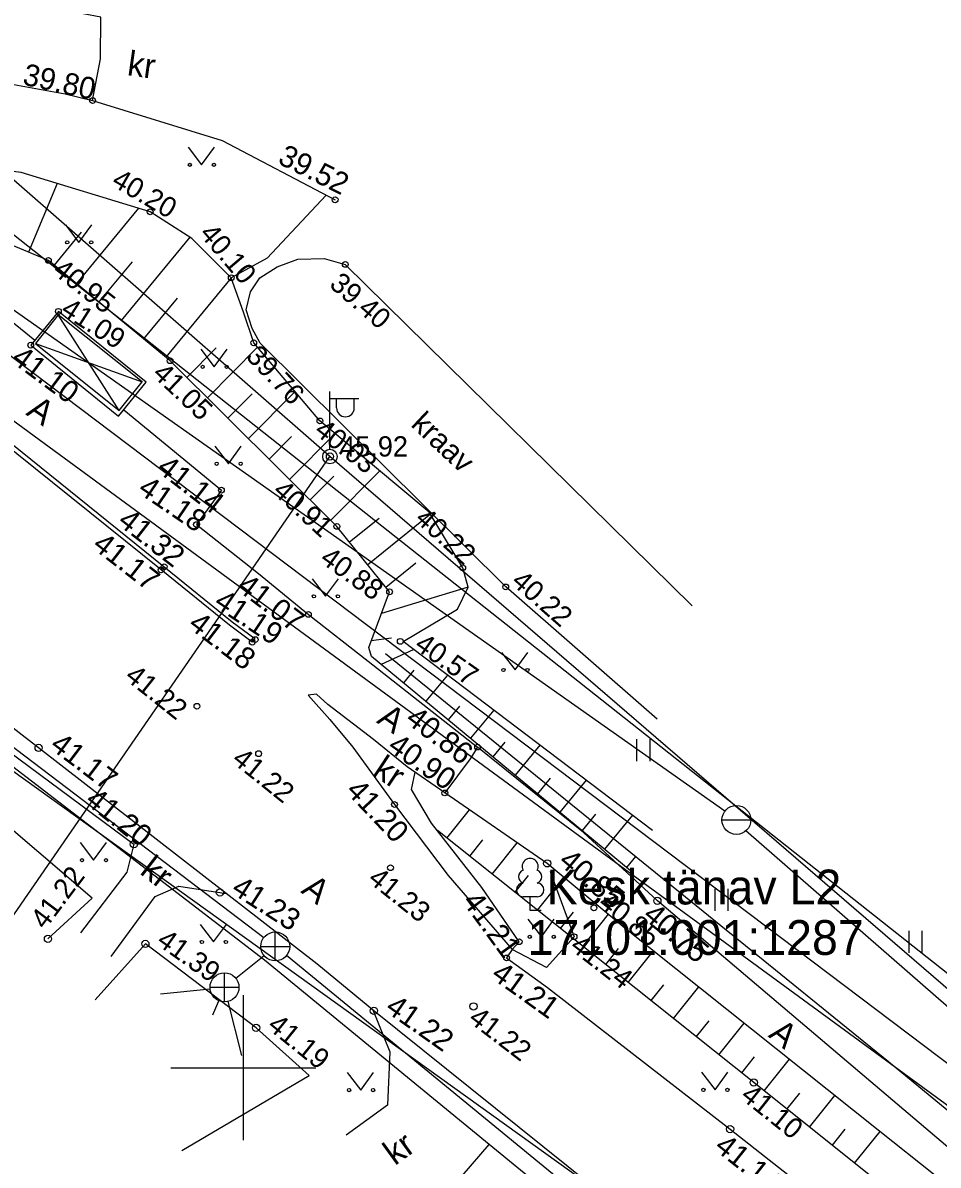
# Model space of a CAD drawing. Extents: x 641898 to 642452, y 6471715 to 6472255.
# Drawn here: x 642092.39 to 642123.98, y 6471996.64 to 6472036.05 of the extents above; entities that cross this region are included whole.
import ezdxf

# ---------------------------------------------------------------- set-up
doc = ezdxf.new("R2010")
doc.units = 0
for name, color, linetype in [('HALJASTUS', 7, 'Continuous'), ('KKAEV', 7, 'Continuous'), ('KORGUS-EH2000', 7, 'Continuous'), ('KTRASS', 7, 'Continuous'), ('MPOHULIIN', 7, 'Continuous'), ('PIIR', 7, 'Continuous'), ('POST', 7, 'Continuous'), ('PUU', 7, 'Continuous'), ('RAJATIS', 7, 'Continuous'), ('RELJEEF', 7, 'Continuous'), ('TEE', 7, 'Continuous'), ('TTRASS', 7, 'Continuous'), ('VEEKOGU', 7, 'Continuous'), ('VKAEV', 7, 'Continuous'), ('VORK', 7, 'Continuous'), ('VTRASS', 7, 'Continuous')]:
    doc.layers.add(name, color=color, linetype=linetype)

msp = doc.modelspace()

# ---------------------------------------------------------------- linework, layer by layer
at = {"layer": 'HALJASTUS'}
for p, q in [((642098.093, 6472031.76), (642098.556, 6472031.154)), ((642098.556, 6472031.154), (642099.002, 6472031.76)), ((642093.86, 6472029.084), (642094.323, 6472028.478)), ((642094.323, 6472028.478), (642094.769, 6472029.084)), ((642098.532, 6472024.791), (642098.996, 6472024.184)), ((642098.996, 6472024.184), (642099.441, 6472024.791)), ((642099.019, 6472021.447), (642099.483, 6472020.84)), ((642099.483, 6472020.84), (642099.928, 6472021.447)), ((642102.374, 6472016.874), (642102.837, 6472016.267)), ((642102.837, 6472016.267), (642103.283, 6472016.874)), ((642108.916, 6472014.333), (642109.379, 6472013.727)), ((642109.379, 6472013.727), (642109.825, 6472014.333)), ((642113.571, 6472011.342), (642113.571, 6472010.581)), ((642114.026, 6472011.342), (642114.026, 6472010.581)), ((642094.367, 6472007.77), (642094.831, 6472007.163)), ((642094.831, 6472007.163), (642095.276, 6472007.77)), ((642116.272, 6472006.171), (642116.272, 6472005.41)), ((642116.728, 6472006.171), (642116.728, 6472005.41)), ((642098.508, 6472004.949), (642098.971, 6472004.342)), ((642098.971, 6472004.342), (642099.417, 6472004.949)), ((642109.824, 6472005.124), (642110.288, 6472004.517)), ((642110.288, 6472004.517), (642110.733, 6472005.124)), ((642122.968, 6472004.731), (642122.968, 6472003.97)), ((642123.423, 6472004.731), (642123.423, 6472003.97)), ((642103.588, 6471999.837), (642104.051, 6471999.23)), ((642104.051, 6471999.23), (642104.497, 6471999.837)), ((642115.818, 6471999.844), (642116.281, 6471999.237)), ((642116.281, 6471999.237), (642116.727, 6471999.844))]:
    msp.add_line(p, q, dxfattribs=at)
for points in [[(642102.863, 6472030.108), (642100.826, 6472027.93), (642099.583, 6472027.26)], [(642132.112, 6471992.094), (642122.27, 6472000.206), (642104.909, 6472014.278)], [(642093.257, 6472004.451), (642094.782, 6472005.85), (642085.481, 6472013.799), (642083.722, 6472011.351)], [(642110.588, 6472006.783), (642110.731, 6472006.388), (642111.416, 6472004.523), (642110.463, 6472003.463), (642109.282, 6472004.08)], [(642097.873, 6471997.144), (642102.276, 6471999.739), (642100.441, 6472001.377), (642096.619, 6472004.274), (642094.883, 6472002.346)]]:
    msp.add_lwpolyline(points, dxfattribs=at)
for centre in [(642098.155, 6472031.154), (642098.984, 6472031.154), (642093.922, 6472028.478), (642094.751, 6472028.478), (642098.595, 6472024.184), (642099.423, 6472024.184), (642099.082, 6472020.84), (642099.91, 6472020.84), (642102.436, 6472016.267), (642103.265, 6472016.267), (642108.978, 6472013.727), (642109.807, 6472013.727), (642094.43, 6472007.163), (642095.259, 6472007.163), (642109.887, 6472004.517), (642110.715, 6472004.517), (642098.57, 6472004.342), (642099.399, 6472004.342), (642103.65, 6471999.23), (642104.479, 6471999.23), (642115.88, 6471999.237), (642116.709, 6471999.237)]:
    msp.add_circle(centre, 0.055, dxfattribs=at)
at = {"layer": 'KKAEV'}
for p, q in [((642101.104, 6472003.687), (642101.104, 6472004.687)), ((642100.604, 6472004.187), (642101.604, 6472004.187)), ((642099.35, 6472002.276), (642099.35, 6472003.276)), ((642098.85, 6472002.776), (642099.85, 6472002.776))]:
    msp.add_line(p, q, dxfattribs=at)
for centre in [(642101.104, 6472004.187), (642099.35, 6472002.776)]:
    msp.add_circle(centre, 0.5, dxfattribs=at)
at = {"layer": 'KORGUS-EH2000'}
for centre, radius in [((642094.797, 6472033.371), 0.1), ((642103.168, 6472029.948), 0.1), ((642096.784, 6472029.532), 0.1), ((642093.272, 6472027.857), 0.1), ((642103.52, 6472027.718), 0.1), ((642099.583, 6472027.26), 0.1), ((642093.616, 6472026.099), 0.1), ((642092.663, 6472024.932), 0.1), ((642100.36, 6472025.014), 0.1), ((642097.472, 6472024.394), 0.1), ((642102.645, 6472022.318), 0.1), ((642102.99, 6472021.089), 0.125), ((642099.243, 6472019.93), 0.1), ((642098.383, 6472018.742), 0.1), ((642103.229, 6472018.679), 0.1), ((642097.162, 6472017.177), 0.1), ((642097.268, 6472017.288), 0.1), ((642107.574, 6472017.251), 0.1), ((642109.056, 6472016.59), 0.1), ((642105.049, 6472016.421), 0.1), ((642102.245, 6472015.643), 0.1), ((642100.309, 6472014.686), 0.1), ((642100.411, 6472014.774), 0.1), ((642105.418, 6472014.713), 0.1), ((642098.399, 6472012.473), 0.1), ((642092.935, 6472011.037), 0.125), ((642108.086, 6472011.066), 0.1), ((642100.527, 6472010.838), 0.1), ((642106.954, 6472009.482), 0.1), ((642105.217, 6472009.083), 0.1), ((642096.224, 6472007.717), 0.125), ((642105.079, 6472006.902), 0.1), ((642110.49, 6472007.053), 0.125), ((642099.193, 6472006.05), 0.125), ((642114.29, 6472005.762), 0.125), ((642112.103, 6472005.517), 0.1), ((642093.257, 6472004.451), 0.125), ((642111.416, 6472004.523), 0.1), ((642096.619, 6472004.274), 0.125), ((642109.519, 6472004.348), 0.1), ((642109.088, 6472003.791), 0.1), ((642104.507, 6472001.966), 0.125), ((642107.944, 6472002.118), 0.125), ((642100.441, 6472001.377), 0.125), ((642117.617, 6471999.493), 0.125), ((642116.8, 6471997.886), 0.125)]:
    msp.add_circle(centre, radius, dxfattribs=at)
at = {"layer": 'KTRASS'}
for points in [[(642100.706, 6472004.489), (642071.965, 6472026.311)], [(642099.74, 6472003.089), (642100.714, 6472003.874)], [(642136.804, 6471974.904), (642101.491, 6472003.87)], [(642097.14, 6472002.555), (642098.852, 6472002.726)], [(642098.951, 6472001.825), (642099.156, 6472002.315)], [(642099.944, 6472000.422), (642099.472, 6472002.291)]]:
    msp.add_lwpolyline(points, dxfattribs=at)
at = {"layer": 'MPOHULIIN'}
msp.add_line((642090.685, 6472003.265), (642102.99, 6472021.089), dxfattribs=at)
msp.add_lwpolyline([(642355.522, 6471813.313), (642331.534, 6471832.393), (642302.222, 6471855.921), (642271.629, 6471880.301), (642234.793, 6471909.555), (642198.436, 6471939.015), (642169.975, 6471961.956), (642133.076, 6471995.171), (642102.99, 6472021.089), (642074.552, 6472045.947), (642044.597, 6472041.824), (642019.939, 6472060.923), (641980.015, 6472091.706), (641945.513, 6472065.466), (641932.178, 6472056.628)], dxfattribs=at)
at = {"layer": 'PIIR'}
for p, q in [((642148.4, 6471984.2), (642083.42, 6472035.57)), ((642079.91, 6472031.22), (642111.27, 6472008.25)), ((642068.76, 6472026.95), (642119.65, 6471990.44)), ((642111.27, 6472008.25), (642146.78, 6471982.26))]:
    msp.add_line(p, q, dxfattribs=at)
at = {"layer": 'POST'}
for p, q in [((642102.99, 6472021.339), (642102.99, 6472023.339)), ((642102.99, 6472023.089), (642103.99, 6472023.089)), ((642103.217, 6472022.768), (642103.217, 6472023.089)), ((642103.829, 6472022.768), (642103.829, 6472023.089))]:
    msp.add_line(p, q, dxfattribs=at)
msp.add_circle((642102.99, 6472021.089), 0.25, dxfattribs=at)
msp.add_arc((642103.523, 6472022.768), 0.306, 180, 0, dxfattribs=at)
at = {"layer": 'PUU'}
for p, q in [((642110.14, 6472005.9), (642109.66, 6472005.9)), ((642110.14, 6472005.9), (642109.66, 6472005.9)), ((642109.9, 6472005.425), (642109.9, 6472005.9)), ((642109.9, 6472005.425), (642109.9, 6472005.9)), ((642110.28, 6472005.425), (642109.9, 6472005.425)), ((642110.28, 6472005.425), (642109.9, 6472005.425))]:
    msp.add_line(p, q, dxfattribs=at)
for centre, radius, start, end in [((642109.9, 6472006.945), 0.277, 332.5799, 207.4201), ((642109.9, 6472006.945), 0.277, 332.5799, 207.4201), ((642109.73, 6472006.598), 0.233, 109.0217, 253.1415), ((642109.73, 6472006.598), 0.233, 109.0217, 253.1415), ((642110.07, 6472006.598), 0.233, 286.8508, 70.9859), ((642110.07, 6472006.598), 0.233, 286.8508, 70.9859), ((642109.663, 6472006.137), 0.238, 90.0016, 269.3953), ((642109.663, 6472006.137), 0.238, 90.0016, 269.3953), ((642110.137, 6472006.137), 0.238, 270.6047, 89.9984), ((642110.137, 6472006.137), 0.238, 270.6047, 89.9984)]:
    msp.add_arc(centre, radius, start, end, dxfattribs=at)
at = {"layer": 'RAJATIS'}
for points in [[(642093.616, 6472026.099), (642092.663, 6472024.932), (642095.692, 6472022.486), (642096.645, 6472023.653), (642093.616, 6472026.099)], [(642093.613, 6472025.98), (642092.823, 6472024.99), (642095.718, 6472022.68), (642096.508, 6472023.67), (642093.613, 6472025.98)], [(642095.718, 6472022.68), (642093.613, 6472025.98)], [(642092.823, 6472024.99), (642096.508, 6472023.67)]]:
    msp.add_lwpolyline(points, dxfattribs=at)
at = {"layer": 'RELJEEF'}
for p, q in [((642093.576, 6472030.513), (642092.586, 6472028.144)), ((642096.382, 6472029.655), (642094.241, 6472027.058)), ((642094.408, 6472028.833), (642093.47, 6472027.694)), ((642098.151, 6472028.656), (642095.784, 6472025.786)), ((642096.158, 6472027.811), (642095.013, 6472026.422)), ((642099.586, 6472027.252), (642097.327, 6472024.513)), ((642097.716, 6472026.556), (642096.556, 6472025.149)), ((642099.062, 6472024.843), (642098.049, 6472023.822)), ((642100.49, 6472024.861), (642098.758, 6472023.117)), ((642100.303, 6472023.254), (642099.468, 6472022.413)), ((642101.788, 6472023.33), (642100.178, 6472021.708)), ((642103.168, 6472021.882), (642101.597, 6472020.299)), ((642101.662, 6472021.784), (642100.887, 6472021.004)), ((642103.123, 6472020.417), (642102.307, 6472019.594)), ((642104.71, 6472020.596), (642103.016, 6472018.89)), ((642106.459, 6472019.098), (642104.296, 6472017.355)), ((642104.684, 6472018.952), (642103.669, 6472018.134)), ((642105.952, 6472017.405), (642104.924, 6472016.576)), ((642107.757, 6472016.588), (642104.768, 6472015.671)), ((642105.117, 6472014.826), (642104.418, 6472014.735)), ((642105.865, 6472014.42), (642104.757, 6472013.92)), ((642105.889, 6472013.72), (642105.527, 6472013.283)), ((642107.048, 6472013.552), (642106.298, 6472012.645)), ((642107.457, 6472012.477), (642107.068, 6472012.008)), ((642108.643, 6472012.342), (642107.839, 6472011.37)), ((642109.025, 6472011.235), (642108.609, 6472010.733)), ((642110.238, 6472011.132), (642109.379, 6472010.095)), ((642110.592, 6472009.992), (642110.15, 6472009.457)), ((642111.832, 6472009.922), (642110.92, 6472008.82)), ((642107.024, 6472007.925), (642107.802, 6472008.899)), ((642112.16, 6472008.75), (642111.691, 6472008.182)), ((642113.427, 6472008.712), (642112.461, 6472007.545)), ((642108.256, 6472007.866), (642107.807, 6472007.302)), ((642108.589, 6472006.679), (642109.454, 6472007.765)), ((642113.231, 6472006.907), (642113.55, 6472007.292)), ((642109.83, 6472006.632), (642109.372, 6472006.056)), ((642110.154, 6472005.434), (642111.063, 6472006.576)), ((642111.384, 6472005.373), (642110.936, 6472004.811)), ((642111.719, 6472004.188), (642112.6, 6472005.295)), ((642112.936, 6472004.112), (642112.501, 6472003.565)), ((642113.284, 6472002.943), (642114.154, 6472004.036)), ((642114.501, 6472002.866), (642114.066, 6472002.32)), ((642114.848, 6472001.697), (642115.718, 6472002.789)), ((642116.065, 6472001.62), (642115.631, 6472001.074)), ((642116.413, 6472000.451), (642117.282, 6472001.543)), ((642117.63, 6472000.374), (642117.195, 6471999.829)), ((642117.977, 6471999.205), (642118.848, 6472000.295)), ((642119.195, 6471999.126), (642118.758, 6471998.58)), ((642119.539, 6471997.955), (642120.413, 6471999.048)), ((642120.757, 6471997.878), (642120.319, 6471997.33)), ((642121.1, 6471996.705), (642121.978, 6471997.802))]:
    msp.add_line(p, q, dxfattribs=at)
for points in [[(642114.124, 6472008.183), (642105.518, 6472014.713), (642107.39, 6472015.826), (642107.757, 6472016.588), (642107.574, 6472017.251), (642106.413, 6472019.175), (642102.645, 6472022.318), (642100.36, 6472025.014), (642100.007, 6472026.072), (642099.583, 6472027.26), (642098.228, 6472028.607), (642096.784, 6472029.532), (642092.335, 6472030.893), (642088.34, 6472031.389), (642082.799, 6472031.819)], [(642113.416, 6472006.754), (642104.425, 6472014.195), (642104.332, 6472014.506), (642105.049, 6472016.421), (642103.229, 6472018.679), (642097.472, 6472024.394), (642093.272, 6472027.857), (642087.606, 6472030.226), (642085.31, 6472031.317), (642082.799, 6472031.819)], [(642146.331, 6471977.025), (642136.065, 6471984.84), (642127.477, 6471991.602), (642117.617, 6471999.493), (642106.697, 6472008.186)]]:
    msp.add_lwpolyline(points, dxfattribs=at)
at = {"layer": 'TEE'}
for points in [[(642127.755, 6471983.25), (642118.56, 6471990.787), (642112.034, 6471995.922), (642104.507, 6472001.966), (642102.538, 6472003.592), (642099.411, 6472006.017), (642092.935, 6472011.037), (642082.111, 6472019.423), (642074.673, 6472025.315), (642072.485, 6472026.831), (642072.011, 6472026.035), (642071.166, 6472026.263), (642070.297, 6472026.346), (642067.3, 6472026.288), (642064.299, 6472028.73), (642063.954, 6472029.272), (642061.62, 6472031.153), (642060.293, 6472030.111), (642058.489, 6472031.665), (642056.171, 6472033.433), (642056.198, 6472033.468), (642053.173, 6472035.891), (642052.964, 6472035.998), (642047.466, 6472040.459)], [(642094.797, 6472033.371), (642095.075, 6472034.807), (642095.084, 6472036.251), (642092.031, 6472036.822), (642088.805, 6472037.164), (642085.522, 6472037.434), (642082.733, 6472037.479), (642081.2, 6472037.267), (642080.962, 6472036.705), (642081.071, 6472035.3), (642080.641, 6472035.163), (642080.76, 6472034.485), (642082.923, 6472034.581), (642085.466, 6472034.656), (642088.646, 6472034.451), (642091.703, 6472033.998), (642093.846, 6472033.603), (642094.797, 6472033.371)], [(642094.797, 6472033.371), (642099.27, 6472031.996), (642103.168, 6472029.948)], [(642086.288, 6472025.937), (642086.385, 6472026.051), (642087.138, 6472025.412), (642091.038, 6472022.294), (642097.256, 6472017.294), (642099.62, 6472015.392), (642100.399, 6472014.806), (642100.309, 6472014.686), (642099.528, 6472015.274), (642097.162, 6472017.177), (642090.944, 6472022.177), (642087.043, 6472025.296), (642086.288, 6472025.937)], [(642091.626, 6472026.063), (642092.804, 6472025.105), (642092.663, 6472024.932), (642095.692, 6472022.486), (642095.871, 6472022.705), (642099.243, 6472019.93), (642098.383, 6472018.742), (642100.529, 6472017.05), (642102.245, 6472015.643), (642104.306, 6472014.032), (642108.086, 6472011.066), (642107.833, 6472010.654), (642106.954, 6472009.482), (642105.653, 6472010.389), (642104.491, 6472011.332), (642102.919, 6472012.534), (642102.524, 6472012.889), (642102.236, 6472012.86), (642102.988, 6472012.012), (642103.776, 6472011.064), (642105.217, 6472009.083), (642107.074, 6472006.634), (642109.282, 6472004.08), (642109.088, 6472003.791), (642110.504, 6472002.773), (642116.8, 6471997.886), (642127.037, 6471989.838)], [(642083.483, 6472012.982), (642084.923, 6472014.693), (642086.799, 6472014.698), (642096.224, 6472007.717), (642095.98, 6472006.753), (642094.378, 6472004.656)], [(642248.038, 6471894.359), (642244.819, 6471896.591), (642243.421, 6471898.287), (642241.287, 6471898.567), (642230.451, 6471907.231), (642220.045, 6471915.264), (642210.382, 6471923.001), (642201.484, 6471930.096), (642191.341, 6471938.065), (642180.941, 6471946.534), (642171.256, 6471954.365), (642153.477, 6471969.856), (642154.958, 6471971.99), (642153.566, 6471973.386), (642153.495, 6471974.667), (642149.137, 6471978.135), (642148.146, 6471977.701), (642140.89, 6471983.962), (642132.244, 6471991.056), (642124.462, 6471997.136), (642114.29, 6472005.762), (642111.738, 6472008.121), (642108.086, 6472011.066)], [(642109.282, 6472004.08), (642109.519, 6472004.348), (642108.233, 6472006.223), (642106.5, 6472008.437), (642105.81, 6472009.597), (642105.933, 6472010.194)], [(642131.75, 6471990.028), (642121.917, 6471997.85), (642113.172, 6472004.818), (642110.49, 6472007.053), (642106.954, 6472009.482)], [(642095.444, 6472003.845), (642096.954, 6472005.912), (642097.779, 6472006.267), (642099.411, 6472006.017)], [(642104.469, 6472001.997), (642105.056, 6472000.546), (642104.976, 6471998.709), (642103.553, 6471997.676)]]:
    msp.add_lwpolyline(points, dxfattribs=at)
at = {"layer": 'TTRASS'}
msp.add_lwpolyline([(642135.042, 6471992.038), (642085.014, 6472029.796)], dxfattribs=at)
at = {"layer": 'VEEKOGU'}
msp.add_lwpolyline([(642114.279, 6472012.032), (642109.056, 6472016.59), (642100.583, 6472025.006), (642100.307, 6472025.509), (642100.095, 6472026.152), (642100.244, 6472026.771), (642100.565, 6472027.255), (642101.171, 6472027.634), (642101.876, 6472027.895), (642102.791, 6472027.921), (642103.52, 6472027.718), (642115.496, 6472015.94)], dxfattribs=at)
at = {"layer": 'VKAEV'}
msp.add_line((642116.519, 6472008.55), (642117.519, 6472008.55), dxfattribs=at)
msp.add_circle((642117.019, 6472008.55), 0.5, dxfattribs=at)
at = {"layer": 'VORK'}
for p, q in [((642100, 6472002.5), (642100, 6471997.5)), ((642097.5, 6472000), (642102.5, 6472000))]:
    msp.add_line(p, q, dxfattribs=at)
at = {"layer": 'VTRASS'}
for points in [[(642116.622, 6472008.855), (642078.542, 6472035.664)], [(642131.146, 6471978.791), (642122.669, 6471985.738), (642108.487, 6471997.357), (642100.73, 6472003.718), (642086.367, 6472014.732), (642072.004, 6472025.747), (642070.54, 6472026.319), (642063.386, 6472027.837), (642057.563, 6472020.38), (642046.398, 6472006.083), (642029.41, 6471984.33), (642022.753, 6471976.477), (642013.331, 6471964.779), (642003.99, 6471953.421), (641999.884, 6471948.226), (641984.12, 6471925.503), (641973.431, 6471931.653), (641967.433, 6471935.11)], [(642152.778, 6471978.827), (642146.383, 6471983.907), (642131.71, 6471995.654), (642117.349, 6472008.175)], [(642106.612, 6471995.349), (642107.557, 6471996.272), (642108.487, 6471997.357)]]:
    msp.add_lwpolyline(points, dxfattribs=at)

# ---------------------------------------------------------------- texts
at = {"layer": 'KORGUS-EH2000'}
for s, height, rotation, p in [('39.80', 0.75, 347.6046, (642092.35, 6472033.93)), ('39.52', 0.75, 333.4349, (642101.151, 6472031.22)), ('40.20', 0.7, 329.7968, (642095.41, 6472030.456)), ('40.10', 0.7, 310.3645, (642098.453, 6472028.76)), ('40.95', 0.7, 322.0869, (642093.377, 6472027.424)), ('39.40', 0.7, 319.0856, (642102.932, 6472026.974)), ('41.09', 0.7, 327.3927, (642093.656, 6472026.026)), ('41.10', 0.75, 323.4604, (642091.95, 6472024.375)), ('39.76', 0.7, 313.4518, (642100.054, 6472024.519)), ('41.05', 0.7, 316.6366, (642096.826, 6472023.894)), ('40.03', 0.7, 321.9919, (642102.409, 6472021.898)), ('41.14', 0.75, 322.2532, (642096.973, 6472020.605)), ('41.18', 0.75, 325.7131, (642096.318, 6472019.861)), ('40.91', 0.7, 317.2702, (642100.974, 6472019.843)), ('41.32', 0.75, 322.0947, (642095.619, 6472018.769)), ('40.22', 0.7, 317.9357, (642105.889, 6472018.879)), ('41.17', 0.75, 322.0735, (642094.751, 6472017.948)), ('40.88', 0.7, 324.0903, (642102.604, 6472017.469)), ('41.07', 0.75, 322.8153, (642099.732, 6472016.509)), ('40.22', 0.7, 318.6283, (642109.209, 6472016.714)), ('41.19', 0.75, 326.3099, (642098.941, 6472015.94)), ('41.18', 0.75, 322.5238, (642098.059, 6472015.211)), ('40.57', 0.7, 325.0607, (642105.865, 6472014.479)), ('41.22', 0.7, 321.4235, (642095.872, 6472013.426)), ('40.86', 0.75, 322.8533, (642105.554, 6472011.938)), ('41.17', 0.75, 322.7987, (642093.285, 6472011.037)), ('40.90', 0.75, 325.0543, (642104.938, 6472010.982)), ('41.22', 0.7, 321.1988, (642099.567, 6472010.561)), ('41.20', 0.75, 313.5338, (642103.503, 6472009.525)), ('41.20', 0.75, 321.3386, (642094.501, 6472009.145)), ('40.85', 0.75, 319.7165, (642110.84, 6472007.053)), ('41.22', 0.7, 53.0438, (642093.156, 6472004.739)), ('41.23', 0.75, 327.1558, (642099.543, 6472006.05)), ('41.23', 0.7, 321.3905, (642104.262, 6472006.438)), ('41.21', 0.75, 306.14, (642107.528, 6472005.739)), ('40.85', 0.7, 321.3402, (642112.204, 6472005.594)), ('40.75', 0.75, 319.8623, (642113.748, 6472005.184)), ('41.39', 0.7, 324.446, (642096.969, 6472004.274)), ('41.24', 0.7, 322.2419, (642111.234, 6472004.107)), ('41.21', 0.75, 324.4207, (642108.515, 6472003.115)), ('41.22', 0.75, 324.888, (642104.857, 6472001.966)), ('41.19', 0.7, 320.9575, (642100.791, 6472001.377)), ('41.22', 0.7, 322.5953, (642107.73, 6472001.611)), ('41.10', 0.7, 321.402, (642117.123, 6471998.956)), ('41.14', 0.75, 321.5154, (642116.22, 6471997.193))]:
    msp.add_text(s, height=height, rotation=rotation, dxfattribs=at).set_placement(p)
msp.add_text('45.92', height=0.7, dxfattribs=at).set_placement((642103.34, 6472021.089))
at = {"layer": 'PIIR'}
for s, p in [('Kesk tänav L2', (642110.47, 6472005.637)), ('17101:001:1287', (642109.812, 6472003.895))]:
    msp.add_text(s, height=1.2, dxfattribs=at).set_placement(p)
at = {"layer": 'TEE'}
for s, rotation, p in [('kr', 352.0371, (642095.964, 6472034.251)), ('A', 325.5327, (642092.468, 6472022.549)), ('A', 325.5327, (642104.569, 6472011.926)), ('kr', 326.4588, (642104.419, 6472010.12)), ('kr', 322.2329, (642096.393, 6472006.716)), ('A', 322.2143, (642101.957, 6472006.065)), ('A', 321.4522, (642118.09, 6472001.088)), ('kr', 35.9776, (642105.229, 6471996.607))]:
    msp.add_text(s, height=0.85, rotation=rotation, dxfattribs=at).set_placement(p)
at = {"layer": 'VEEKOGU'}
msp.add_text('kraav', height=0.75, rotation=316.8012, dxfattribs=at).set_placement((642105.749, 6472022.156))

doc.saveas('drawing.dxf')
